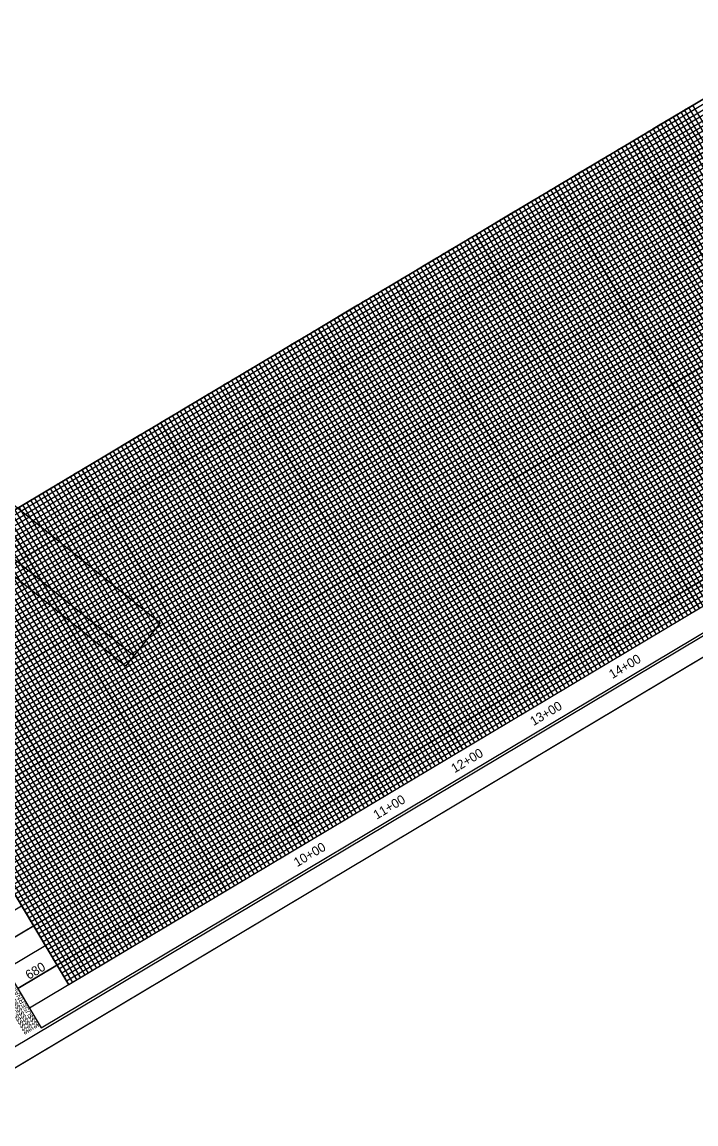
# Model space of a CAD drawing. Extents: x 1487794 to 1489801, y 498102 to 499906.
# Drawn here: x 1488466 to 1489200, y 498102 to 499304 of the extents above; entities that cross this region are included whole.
import ezdxf

# ---------------------------------------------------------------- set-up
doc = ezdxf.new("R2010")
doc.units = 0
for name, color, linetype in [('Exist Vertical Profile Ground Line', 7, 'Continuous'), ('Exist Vertical Profile Horizontal Axis Label Major', 7, 'Continuous'), ('Exist Vertical Profile Vertical Axis Label', 7, 'Continuous'), ('Prop Horizontal Alignment Curve and Spiral Data', 7, 'Continuous'), ('Prop Terminator CELL', 7, 'Continuous'), ('Scratch_Level_6', 7, 'Continuous'), ('Sheet Cutting Line CELL', 7, 'Continuous'), ('Sheet Data Field CELL', 7, 'Continuous'), ('Sheet DOT Grid CELL', 7, 'Continuous'), ('Sheet Plot Border Inside CELL', 7, 'Continuous'), ('Sheet Plot Border Outside CELL', 7, 'Continuous'), ('Sheet Profile CELL', 7, 'Continuous'), ('Sheet Profile Grid Major CELL', 7, 'Continuous'), ('Sheet Profile Grid Middle CELL', 7, 'Continuous'), ('Sheet Sticker Incomplete CELL', 7, 'Continuous')]:
    doc.layers.add(name, color=color, linetype=linetype)

msp = doc.modelspace()

# ---------------------------------------------------------------- linework, layer by layer
at = {"layer": 'Exist Vertical Profile Ground Line'}
msp.add_lwpolyline([(1488356.6, 498126.2), (1489787, 498980.3), (1489246.1, 499886.1), (1487815.7, 499032)], close=True, dxfattribs=at)
at = {"layer": 'Exist Vertical Profile Horizontal Axis Label Major'}
msp.add_lwpolyline([(1488355.7, 498102.3), (1489801.1, 498965.4), (1489239.8, 499905.6), (1487794.3, 499042.5)], close=True, dxfattribs=at)
at = {"layer": 'Exist Vertical Profile Vertical Axis Label'}
msp.add_line((1488355.7, 498102.3), (1489801.1, 498965.4), dxfattribs=at)
at = {"layer": 'Prop Horizontal Alignment Curve and Spiral Data'}
msp.add_lwpolyline([(1488273.7, 498661.9), (1489475.7, 499379.7), (1489719.2, 498971.8), (1488517.2, 498254.1)], close=True, dxfattribs=at)
at = {"layer": 'Prop Terminator CELL'}
msp.add_lwpolyline([(1488230.8, 498636.3), (1487948.8, 499108.5), (1489064.9, 499775), (1489153.9, 499626), (1489135, 499614.7), (1489151.4, 499587.3), (1489342, 499701.1), (1489518.7, 499405.3)], close=True, dxfattribs=at)
at = {"layer": 'Scratch_Level_6'}
msp.add_line((1488587.8, 498612.8), (1487972.3, 499109.2), dxfattribs=at)
msp.add_lwpolyline([(1488578.7, 498601.5), (1487963.2, 499097.8), (1488001.2, 499145), (1488616.7, 498648.6)], close=True, dxfattribs=at)
at = {"layer": 'Sheet Data Field CELL'}
for points in [[(1488230.8, 498636.3), (1489518.7, 499405.3)], [(1489544.3, 499362.4), (1488256.4, 498593.4), (1488282, 498550.4), (1489569.9, 499319.5)], [(1489595.6, 499276.5), (1488307.7, 498507.5), (1488333.3, 498464.6), (1489621.2, 499233.6)], [(1489375.8, 498766.8), (1489132.3, 499174.6), (1489175.2, 499200.2), (1489418.7, 498792.4)], [(1489646.8, 499190.7), (1488358.9, 498421.7), (1488384.6, 498378.7), (1489672.5, 499147.7)], [(1489290, 498715.5), (1489046.4, 499123.3), (1489089.4, 499149), (1489332.9, 498741.1)], [(1489698.1, 499104.8), (1488410.2, 498335.8), (1488435.8, 498292.9), (1489723.7, 499061.9)], [(1489204.1, 498664.2), (1488960.6, 499072.1), (1489003.5, 499097.7), (1489247, 498689.9)], [(1489118.2, 498613), (1488874.7, 499020.8), (1488917.6, 499046.4), (1489161.2, 498638.6)], [(1489749.4, 499018.9), (1488461.5, 498249.9)], [(1489032.4, 498561.7), (1488788.9, 498969.5), (1488831.8, 498995.2), (1489075.3, 498587.3)], [(1488946.5, 498510.4), (1488703, 498918.3), (1488745.9, 498943.9), (1488989.4, 498536.1)], [(1488860.7, 498459.2), (1488617.1, 498867), (1488660.1, 498892.6), (1488903.6, 498484.8)], [(1488774.8, 498407.9), (1488531.3, 498815.7), (1488574.2, 498841.4), (1488817.7, 498433.5)], [(1488688.9, 498356.6), (1488445.4, 498764.5), (1488488.4, 498790.1), (1488731.9, 498382.3)], [(1488603.1, 498305.4), (1488359.6, 498713.2), (1488402.5, 498738.8), (1488646, 498331)], [(1488517.2, 498254.1), (1488273.7, 498661.9), (1488316.6, 498687.6), (1488560.2, 498279.7)], [(1488230.8, 498636.3), (1488474.3, 498228.5)]]:
    msp.add_lwpolyline(points, dxfattribs=at)
at = {"layer": 'Sheet DOT Grid CELL'}
msp.add_line((1488487.1, 498207), (1488487.1, 498207), dxfattribs=at)
at = {"layer": 'Sheet Plot Border Inside CELL'}
for p, q in [((1488243.6, 498614.8), (1489531.5, 499383.8)), ((1489557.1, 499340.9), (1488269.2, 498571.9)), ((1488294.9, 498529), (1489582.7, 499298)), ((1489608.4, 499255.1), (1488320.5, 498486.1)), ((1488346.1, 498443.1), (1489634, 499212.1)), ((1489659.6, 499169.2), (1488371.8, 498400.2)), ((1488397.4, 498357.3), (1489685.3, 499126.3)), ((1489710.9, 499083.3), (1488423, 498314.3)), ((1488448.7, 498271.4), (1489736.5, 499040.4))]:
    msp.add_line(p, q, dxfattribs=at)
for points in [[(1489397.3, 498779.6), (1489153.8, 499187.4), (1489196.7, 499213.1), (1489440.2, 498805.2)], [(1489311.4, 498728.3), (1489067.9, 499136.2), (1489110.8, 499161.8), (1489354.3, 498754)], [(1489225.6, 498677.1), (1488982, 499084.9), (1489025, 499110.5), (1489268.5, 498702.7)], [(1489139.7, 498625.8), (1488896.2, 499033.6), (1488939.1, 499059.3), (1489182.6, 498651.4)], [(1489053.8, 498574.5), (1488810.3, 498982.4), (1488853.3, 499008), (1489096.8, 498600.2)], [(1488968, 498523.3), (1488724.5, 498931.1), (1488767.4, 498956.7), (1489010.9, 498548.9)], [(1488882.1, 498472), (1488638.6, 498879.8), (1488681.5, 498905.5), (1488925.1, 498497.6)], [(1488796.3, 498420.7), (1488552.7, 498828.6), (1488595.7, 498854.2), (1488839.2, 498446.4)], [(1488710.4, 498369.5), (1488466.9, 498777.3), (1488509.8, 498802.9), (1488753.3, 498395.1)], [(1488624.5, 498318.2), (1488381, 498726), (1488424, 498751.7), (1488667.5, 498343.8)], [(1488538.7, 498266.9), (1488295.2, 498674.8), (1488338.1, 498700.4), (1488581.6, 498292.6)]]:
    msp.add_lwpolyline(points, dxfattribs=at)
at = {"layer": 'Sheet Plot Border Outside CELL'}
for p, q in [((1488230.8, 498636.3), (1489518.7, 499405.3)), ((1488256.4, 498593.4), (1489544.3, 499362.4)), ((1488282, 498550.4), (1489569.9, 499319.5)), ((1488307.7, 498507.5), (1489595.6, 499276.5)), ((1488333.3, 498464.6), (1489621.2, 499233.6)), ((1489175.2, 499200.2), (1489418.7, 498792.4)), ((1488358.9, 498421.7), (1489646.8, 499190.7)), ((1489132.3, 499174.6), (1489375.8, 498766.8)), ((1488384.6, 498378.7), (1489672.5, 499147.7)), ((1489089.4, 499149), (1489332.9, 498741.1)), ((1489046.4, 499123.3), (1489290, 498715.5)), ((1488410.2, 498335.8), (1489698.1, 499104.8)), ((1489003.5, 499097.7), (1489247, 498689.9)), ((1488960.6, 499072.1), (1489204.1, 498664.2)), ((1488435.8, 498292.9), (1489723.7, 499061.9)), ((1488917.6, 499046.4), (1489161.2, 498638.6)), ((1488461.5, 498249.9), (1489749.4, 499018.9)), ((1488874.7, 499020.8), (1489118.2, 498613)), ((1488831.8, 498995.2), (1489075.3, 498587.3)), ((1488788.9, 498969.5), (1489032.4, 498561.7)), ((1488745.9, 498943.9), (1488989.4, 498536.1)), ((1488703, 498918.3), (1488946.5, 498510.4)), ((1488660.1, 498892.6), (1488903.6, 498484.8)), ((1488617.1, 498867), (1488860.7, 498459.2)), ((1488574.2, 498841.4), (1488817.7, 498433.5)), ((1488531.3, 498815.7), (1488774.8, 498407.9)), ((1488488.4, 498790.1), (1488731.9, 498382.3)), ((1488445.4, 498764.5), (1488688.9, 498356.6)), ((1488402.5, 498738.8), (1488646, 498331)), ((1488359.6, 498713.2), (1488603.1, 498305.4)), ((1488316.6, 498687.6), (1488560.2, 498279.7)), ((1488273.7, 498661.9), (1488517.2, 498254.1))]:
    msp.add_line(p, q, dxfattribs=at)
at = {"layer": 'Sheet Profile CELL'}
msp.add_lwpolyline([(1488273.7, 498661.9), (1489475.7, 499379.7), (1489719.2, 498971.8), (1488517.2, 498254.1)], close=True, dxfattribs=at)
at = {"layer": 'Sheet Profile Grid Major CELL'}
for points in [[(1488278.8, 498653.4), (1489480.9, 499371.1), (1489478.3, 499375.4), (1488276.3, 498657.6)], [(1488284, 498644.8), (1489486, 499362.5), (1489483.4, 499366.8), (1488281.4, 498649.1)], [(1488291.7, 498631.9), (1489493.7, 499349.6), (1489491.1, 499353.9), (1488289.1, 498636.2)], [(1488296.8, 498623.3), (1489498.8, 499341), (1489496.2, 499345.3), (1488294.2, 498627.6)], [(1488304.5, 498610.4), (1489506.5, 499328.2), (1489503.9, 499332.5), (1488301.9, 498614.7)], [(1488309.6, 498601.8), (1489511.6, 499319.6), (1489509.1, 499323.9), (1488307, 498606.1)], [(1488317.3, 498589), (1489519.3, 499306.7), (1489516.7, 499311), (1488314.7, 498593.3)], [(1488322.4, 498580.4), (1489524.4, 499298.1), (1489521.9, 499302.4), (1488319.8, 498584.7)], [(1488327.5, 498571.8), (1489529.6, 499289.5)], [(1488332.7, 498563.2), (1489534.7, 499280.9), (1489532.1, 499285.2), (1488330.1, 498567.5)], [(1488340.4, 498550.3), (1489542.4, 499268.1), (1489537.3, 499276.6), (1488335.2, 498558.9)], [(1488345.5, 498541.7), (1489547.5, 499259.5), (1489544.9, 499263.8), (1488342.9, 498546)], [(1488353.2, 498528.9), (1489555.2, 499246.6), (1489550.1, 499255.2), (1488348, 498537.4)], [(1488358.3, 498520.3), (1489560.3, 499238), (1489557.8, 499242.3), (1488355.7, 498524.6)], [(1488366, 498507.4), (1489568, 499225.1), (1489562.9, 499233.7), (1488360.9, 498516)], [(1488371.1, 498498.8), (1489573.1, 499216.5), (1489570.6, 499220.8), (1488368.6, 498503.1)], [(1488378.8, 498485.9), (1489580.8, 499203.7), (1489575.7, 499212.3), (1488373.7, 498494.5)], [(1488383.9, 498477.3), (1489586, 499195.1), (1489583.4, 499199.4), (1488381.4, 498481.6)], [(1489423, 498795), (1489179.5, 499202.8), (1489183.8, 499205.4), (1489427.3, 498797.5)], [(1489431.6, 498800.1), (1489188.1, 499207.9), (1489192.4, 499210.5), (1489435.9, 498802.7)], [(1488391.6, 498464.5), (1489593.6, 499182.2), (1489588.5, 499190.8), (1488386.5, 498473.1)], [(1489401.6, 498782.2), (1489158.1, 499190), (1489162.3, 499192.6), (1489405.9, 498784.7)], [(1489410.2, 498787.3), (1489166.6, 499195.1), (1489170.9, 499197.7), (1489414.4, 498789.9)], [(1488396.7, 498455.9), (1489598.8, 499173.6), (1489596.2, 499177.9), (1488394.2, 498460.2)], [(1489380.1, 498769.3), (1489136.6, 499177.2), (1489140.9, 499179.7), (1489384.4, 498771.9)], [(1489388.7, 498774.5), (1489145.2, 499182.3), (1489149.5, 499184.9), (1489393, 498777)], [(1488404.4, 498443), (1489606.5, 499160.7), (1489601.3, 499169.3), (1488399.3, 498451.6)], [(1489358.6, 498756.5), (1489115.1, 499164.4), (1489119.4, 499166.9), (1489362.9, 498759.1)], [(1489367.2, 498761.7), (1489123.7, 499169.5), (1489128, 499172), (1489371.5, 498764.2)], [(1488409.6, 498434.4), (1489611.6, 499152.2), (1489609, 499156.4), (1488407, 498438.7)], [(1489337.2, 498743.7), (1489093.7, 499151.5), (1489098, 499154.1), (1489341.5, 498746.3)], [(1489345.8, 498748.8), (1489102.2, 499156.7), (1489106.5, 499159.2), (1489350.1, 498751.4)], [(1488417.3, 498421.5), (1489619.3, 499139.3), (1489614.2, 499147.9), (1488412.1, 498430.1)], [(1489315.7, 498730.9), (1489072.2, 499138.7), (1489076.5, 499141.3), (1489320, 498733.5)], [(1489324.3, 498736), (1489080.8, 499143.8), (1489085.1, 499146.4), (1489328.6, 498738.6)], [(1488422.4, 498413), (1489624.4, 499130.7), (1489621.8, 499135), (1488419.8, 498417.2)], [(1489294.2, 498718.1), (1489050.7, 499125.9), (1489055, 499128.5), (1489298.5, 498720.6)], [(1489302.8, 498723.2), (1489059.3, 499131), (1489063.6, 499133.6), (1489307.1, 498725.8)], [(1488430.1, 498400.1), (1489632.1, 499117.8), (1489627, 499126.4), (1488424.9, 498408.7)], [(1489272.8, 498705.3), (1489029.3, 499113.1), (1489033.6, 499115.7), (1489277.1, 498707.8)], [(1489281.4, 498710.4), (1489037.9, 499118.2), (1489042.1, 499120.8), (1489285.7, 498713)], [(1488435.2, 498391.5), (1489637.2, 499109.2), (1489634.7, 499113.5), (1488432.6, 498395.8)], [(1488442.9, 498378.6), (1489644.9, 499096.3), (1489639.8, 499104.9), (1488437.8, 498387.2)], [(1489251.3, 498692.4), (1489007.8, 499100.3), (1489012.1, 499102.8), (1489255.6, 498695)], [(1489259.9, 498697.6), (1489016.4, 499105.4), (1489020.7, 499108), (1489264.2, 498700.1)], [(1488448, 498370), (1489650, 499087.8), (1489647.5, 499092.1), (1488445.5, 498374.3)], [(1489238.4, 498684.8), (1488994.9, 499092.6), (1488999.2, 499095.1), (1489242.7, 498687.3)], [(1488455.7, 498357.1), (1489657.7, 499074.9), (1489652.6, 499083.5), (1488450.6, 498365.7)], [(1489217, 498671.9), (1488973.5, 499079.8), (1488977.7, 499082.3), (1489221.3, 498674.5)], [(1489229.9, 498679.6), (1488986.3, 499087.5), (1488990.6, 499090), (1489234.1, 498682.2)], [(1488460.8, 498348.6), (1489662.9, 499066.3), (1489660.3, 499070.6), (1488458.3, 498352.9)], [(1489195.5, 498659.1), (1488952, 499066.9), (1488956.3, 499069.5), (1489199.8, 498661.7)], [(1489208.4, 498666.8), (1488964.9, 499074.6), (1488969.2, 499077.2), (1489212.7, 498669.4)], [(1488483.9, 498309.9), (1488481.3, 498314.2), (1489683.4, 499031.9), (1489678.2, 499040.5), (1488476.2, 498322.8), (1488473.6, 498327.1), (1489675.7, 499044.8), (1489673.1, 499049.1), (1488471.1, 498331.4), (1488468.5, 498335.7), (1489670.5, 499053.4), (1489665.4, 499062), (1488463.4, 498344.3)], [(1489174, 498646.3), (1488930.5, 499054.1), (1488934.8, 499056.7), (1489178.3, 498648.9)], [(1489186.9, 498654), (1488943.4, 499061.8), (1488947.7, 499064.4), (1489191.2, 498656.6)], [(1489152.6, 498633.5), (1488909.1, 499041.3), (1488913.4, 499043.9), (1489156.9, 498636.1)], [(1489165.5, 498641.2), (1488921.9, 499049), (1488926.2, 499051.6), (1489169.8, 498643.7)], [(1489131.1, 498620.7), (1488887.6, 499028.5), (1488891.9, 499031.1), (1489135.4, 498623.2)], [(1489144, 498628.4), (1488900.5, 499036.2), (1488904.8, 499038.8), (1489148.3, 498630.9)], [(1488514.7, 498258.4), (1489716.7, 498976.1), (1489714.1, 498980.4), (1488512.1, 498262.7), (1488509.5, 498267), (1489711.6, 498984.7), (1489709, 498989), (1488507, 498271.3), (1488504.4, 498275.6), (1488501.8, 498279.9), (1489703.9, 498997.6), (1489701.3, 499001.9), (1488499.3, 498284.2), (1488496.7, 498288.5), (1489698.7, 499006.2), (1489696.2, 499010.5), (1488494.2, 498292.7), (1488491.6, 498297), (1488489, 498301.3), (1489691.1, 499019.1), (1489688.5, 499023.4), (1488486.5, 498305.6), (1488483.9, 498309.9), (1489685.9, 499027.7)], [(1489122.5, 498615.5), (1488879, 499023.4), (1488883.3, 499025.9), (1489126.8, 498618.1)], [(1489101.1, 498602.7), (1488857.5, 499010.6), (1488861.8, 499013.1), (1489105.4, 498605.3)], [(1489109.7, 498607.9), (1488866.1, 499015.7), (1488870.4, 499018.2), (1489113.9, 498610.4)], [(1489079.6, 498589.9), (1488836.1, 498997.7), (1488840.4, 499000.3), (1489083.9, 498592.5)], [(1489088.2, 498595), (1488844.7, 499002.9), (1488849, 499005.4), (1489092.5, 498597.6)], [(1489058.1, 498577.1), (1488814.6, 498984.9), (1488818.9, 498987.5), (1489062.4, 498579.7)], [(1489066.7, 498582.2), (1488823.2, 498990), (1488827.5, 498992.6), (1489071, 498584.8)], [(1489036.7, 498564.3), (1488793.2, 498972.1), (1488797.4, 498974.7), (1489041, 498566.8)], [(1489045.3, 498569.4), (1488801.7, 498977.2), (1488806, 498979.8), (1489049.6, 498572)], [(1489015.2, 498551.5), (1488771.7, 498959.3), (1488776, 498961.9), (1489019.5, 498554)], [(1489023.8, 498556.6), (1488780.3, 498964.4), (1488784.6, 498967), (1489028.1, 498559.2)], [(1488993.7, 498538.6), (1488750.2, 498946.5), (1488754.5, 498949), (1488998, 498541.2)], [(1489002.3, 498543.8), (1488758.8, 498951.6), (1488763.1, 498954.2), (1489006.6, 498546.3)], [(1488972.3, 498525.8), (1488728.8, 498933.7), (1488733.1, 498936.2), (1488976.6, 498528.4)], [(1488980.9, 498531), (1488737.3, 498938.8), (1488741.6, 498941.3), (1488985.2, 498533.5)], [(1488950.8, 498513), (1488707.3, 498920.8), (1488711.6, 498923.4), (1488955.1, 498515.6)], [(1488959.4, 498518.1), (1488715.9, 498926), (1488720.2, 498928.5), (1488963.7, 498520.7)], [(1488929.3, 498500.2), (1488685.8, 498908), (1488690.1, 498910.6), (1488933.6, 498502.8)], [(1488937.9, 498505.3), (1488694.4, 498913.1), (1488698.7, 498915.7), (1488942.2, 498507.9)], [(1488916.5, 498492.5), (1488673, 498900.3), (1488677.2, 498902.9), (1488920.8, 498495.1)], [(1488895, 498479.7), (1488651.5, 498887.5), (1488655.8, 498890.1), (1488899.3, 498482.3)], [(1488907.9, 498487.4), (1488664.4, 498895.2), (1488668.7, 498897.8), (1488912.2, 498489.9)], [(1488873.5, 498466.9), (1488630, 498874.7), (1488634.3, 498877.3), (1488877.8, 498469.4)], [(1488886.4, 498474.6), (1488642.9, 498882.4), (1488647.2, 498885), (1488890.7, 498477.1)], [(1488852.1, 498454.1), (1488608.6, 498861.9), (1488612.9, 498864.4), (1488856.4, 498456.6)], [(1488865, 498461.7), (1488621.4, 498869.6), (1488625.7, 498872.1), (1488869.2, 498464.3)], [(1488830.6, 498441.2), (1488587.1, 498849.1), (1488591.4, 498851.6), (1488834.9, 498443.8)], [(1488843.5, 498448.9), (1488600, 498856.8), (1488604.3, 498859.3), (1488847.8, 498451.5)], [(1488809.1, 498428.4), (1488565.6, 498836.2), (1488569.9, 498838.8), (1488813.4, 498431)], [(1488822, 498436.1), (1488578.5, 498843.9), (1488582.8, 498846.5), (1488826.3, 498438.7)], [(1488800.6, 498423.3), (1488557, 498831.1), (1488561.3, 498833.7), (1488804.9, 498425.9)], [(1488779.1, 498410.5), (1488535.6, 498818.3), (1488539.9, 498820.9), (1488783.4, 498413)], [(1488787.7, 498415.6), (1488544.2, 498823.4), (1488548.5, 498826), (1488792, 498418.2)], [(1488757.6, 498397.7), (1488514.1, 498805.5), (1488518.4, 498808.1), (1488761.9, 498400.2)], [(1488766.2, 498402.8), (1488522.7, 498810.6), (1488527, 498813.2), (1488770.5, 498405.3)], [(1488736.2, 498384.8), (1488492.6, 498792.7), (1488496.9, 498795.2), (1488740.5, 498387.4)], [(1488744.8, 498390), (1488501.2, 498797.8), (1488505.5, 498800.4), (1488749, 498392.5)], [(1488714.7, 498372), (1488471.2, 498779.9), (1488475.5, 498782.4), (1488719, 498374.6)], [(1488723.3, 498377.2), (1488479.8, 498785), (1488484.1, 498787.5), (1488727.6, 498379.7)], [(1488693.2, 498359.2), (1488449.7, 498767), (1488454, 498769.6), (1488697.5, 498361.8)], [(1488701.8, 498364.3), (1488458.3, 498772.2), (1488462.6, 498774.7), (1488706.1, 498366.9)], [(1488671.8, 498346.4), (1488428.3, 498754.2), (1488432.5, 498756.8), (1488676.1, 498349)], [(1488680.4, 498351.5), (1488436.8, 498759.3), (1488441.1, 498761.9), (1488684.7, 498354.1)], [(1488650.3, 498333.6), (1488406.8, 498741.4), (1488411.1, 498744), (1488654.6, 498336.1)], [(1488658.9, 498338.7), (1488415.4, 498746.5), (1488419.7, 498749.1), (1488663.2, 498341.3)], [(1488628.8, 498320.8), (1488385.3, 498728.6), (1488389.6, 498731.2), (1488633.1, 498323.3)], [(1488637.4, 498325.9), (1488393.9, 498733.7), (1488398.2, 498736.3), (1488641.7, 498328.4)], [(1488616, 498313.1), (1488372.4, 498720.9), (1488376.7, 498723.5), (1488620.3, 498315.6)], [(1488594.5, 498300.3), (1488351, 498708.1), (1488355.3, 498710.6), (1488598.8, 498302.8)], [(1488607.4, 498307.9), (1488363.9, 498715.8), (1488368.2, 498718.3), (1488611.7, 498310.5)], [(1488573, 498287.4), (1488329.5, 498695.3), (1488333.8, 498697.8), (1488577.3, 498290)], [(1488585.9, 498295.1), (1488342.4, 498703), (1488346.7, 498705.5), (1488590.2, 498297.7)], [(1488551.6, 498274.6), (1488308.1, 498682.4), (1488312.3, 498685), (1488555.9, 498277.2)], [(1488564.4, 498282.3), (1488320.9, 498690.1), (1488325.2, 498692.7), (1488568.7, 498284.9)], [(1488530.1, 498261.8), (1488286.6, 498669.6), (1488290.9, 498672.2), (1488534.4, 498264.4)], [(1488543, 498269.5), (1488299.5, 498677.3), (1488303.8, 498679.9), (1488547.3, 498272.1)], [(1488521.5, 498256.7), (1488278, 498664.5), (1488282.3, 498667.1), (1488525.8, 498259.2)]]:
    msp.add_lwpolyline(points, dxfattribs=at)
at = {"layer": 'Sheet Profile Grid Middle CELL'}
for p, q in [((1488230.8, 498636.3), (1489518.7, 499405.3)), ((1489762.2, 498997.5), (1488474.3, 498228.5)), ((1488487.1, 498207), (1488487.1, 498207)), ((1488487.1, 498207), (1488487.1, 498207)), ((1488487.1, 498207), (1488487.1, 498207)), ((1488487.1, 498207), (1488487.1, 498207)), ((1488487.1, 498207), (1488487.1, 498207))]:
    msp.add_line(p, q, dxfattribs=at)
msp.add_lwpolyline([(1489236.7, 499877.5), (1487948.8, 499108.5), (1488487.1, 498207), (1489775, 498976)], close=True, dxfattribs=at)

# ---------------------------------------------------------------- texts
at = {"layer": 'Sheet Cutting Line CELL'}
for s, p in [('14+00', (1489109.3, 498587.3)), ('13+00', (1489023.4, 498536)), ('12+00', (1488937.4, 498484.6)), ('11+00', (1488852.6, 498434)), ('10+00', (1488765.9, 498382.2))]:
    msp.add_text(s, height=10, rotation=30.8418, dxfattribs=at).set_placement(p)
at = {"layer": 'Sheet DOT Grid CELL'}
for s, p in [('$$$$$$$$$$$$$$$$DGN$$$$$$$$$$$$$$$$', (1488479.3, 498205.1)), ('$$$$$$SYSTIME$$$$$', (1488474.1, 498202)), ('$$$$USERNAME$$$$', (1488485, 498208.5))]:
    msp.add_text(s, height=5.25, rotation=120.8418, dxfattribs=at).set_placement(p)
at = {"layer": 'Sheet Sticker Incomplete CELL'}
msp.add_text('680', height=10, rotation=30.8418, dxfattribs=at).set_placement((1488473.6, 498259.4))

doc.saveas('drawing.dxf')
